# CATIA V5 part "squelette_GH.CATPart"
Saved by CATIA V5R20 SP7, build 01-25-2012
Part number: squelette_GH
Publications: "G'", "GG'", "barre_GH", "axe.pivot.G", "axe.pivot.H", "Plan.pivots"
Bounding box of the stored display mesh (mm): x -2 to 22.1, y -52 to 0, z -9.5 to -9.5
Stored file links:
  F:\IAO_Renouveau\squelette_GH.CATPart
  F:\IAO_Renouveau\squelette.CATProduct
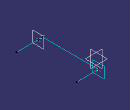
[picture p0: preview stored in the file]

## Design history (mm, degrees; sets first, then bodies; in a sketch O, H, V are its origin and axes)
Set1
  Plane1 "plan.-2": linked copy from another document
  Point1 "G": linked copy from another document
  Point2 "H": linked copy from another document
  Plane2 "Plan.2,1": linked copy from another document
Set2
  Point3 "G'": type OnPlane, Support Plane1, H -52, V -9.5, Direction (0, 1, 0)
  Line1 "GG'": type PtPt, FirstPoint Point3, SecondPoint Point1
  Line2 "barre_GH": type PtPt, FirstPoint Point3, SecondPoint Point2, Support Plane1
  Line3 "axe.pivot.G": type Normal, RefPoint Point1, RefSkin Plane2, Start 0, End 20
  Line4 "axe.pivot.H": type Normal, RefPoint Point2, RefSkin Plane1, Start 0, End 20
  Plane3 "Plan.pivots": type Offset, RefPlane Plane1, Offset 0
Body1 (main body)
